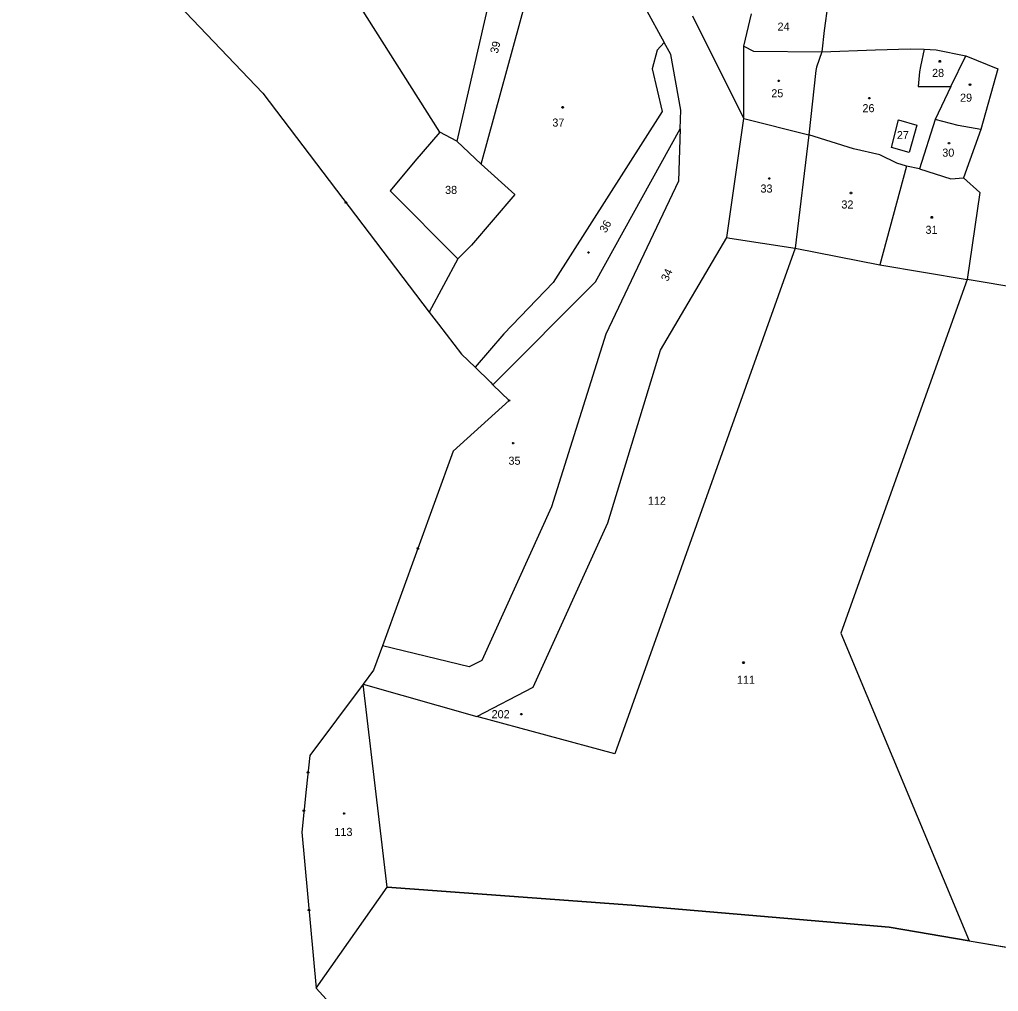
# Model space of a CAD drawing. Extents: x -841286 to -834997, y -1020681 to -1017810.
# Drawn here: x -838838.7 to -838632.6, y -1019442.2 to -1019237.6 of the extents above; entities that cross this region are included whole.
import ezdxf

# ---------------------------------------------------------------- set-up
doc = ezdxf.new("R2010")
doc.units = 0
for name, color, linetype in [('NERES_HRA', 7, 'Continuous'), ('OVNE_POP', 7, 'Continuous'), ('OVNE_PRE', 7, 'Continuous'), ('OVNE_SET', 7, 'Continuous'), ('OVNI_SET', 7, 'Continuous')]:
    doc.layers.add(name, color=color, linetype=linetype)

msp = doc.modelspace()

# ---------------------------------------------------------------- linework, layer by layer
at = {"layer": 'NERES_HRA'}
for points in [[(-838735.55, -1019317.63), (-838735.46, -1019317.78), (-838735.55, -1019317.93), (-838735.73, -1019317.93), (-838735.82, -1019317.78), (-838735.73, -1019317.63)], [(-838732.97, -1019383.7), (-838732.88, -1019383.85), (-838732.97, -1019384), (-838733.15, -1019384), (-838733.24, -1019383.85), (-838733.15, -1019383.7)]]:
    msp.add_lwpolyline(points, close=True, dxfattribs=at)
at = {"layer": 'OVNE_POP'}
for points in [[(-838644.84, -1019246.23), (-838644.75, -1019246.38), (-838644.84, -1019246.53), (-838645.02, -1019246.53), (-838645.11, -1019246.38), (-838645.02, -1019246.23)], [(-838678.75, -1019250.35), (-838678.66, -1019250.5), (-838678.75, -1019250.65), (-838678.93, -1019250.65), (-838679.02, -1019250.5), (-838678.93, -1019250.35)], [(-838638.49, -1019251.16), (-838638.4, -1019251.31), (-838638.49, -1019251.46), (-838638.67, -1019251.46), (-838638.76, -1019251.31), (-838638.67, -1019251.16)], [(-838659.69, -1019254.01), (-838659.6, -1019254.16), (-838659.69, -1019254.31), (-838659.87, -1019254.31), (-838659.96, -1019254.16), (-838659.87, -1019254.01)], [(-838724.28, -1019255.92), (-838724.19, -1019256.07), (-838724.28, -1019256.22), (-838724.46, -1019256.22), (-838724.55, -1019256.07), (-838724.46, -1019255.92)], [(-838642.91, -1019263.46), (-838642.82, -1019263.61), (-838642.91, -1019263.76), (-838643.09, -1019263.76), (-838643.18, -1019263.61), (-838643.09, -1019263.46)], [(-838680.77, -1019270.93), (-838680.68, -1019271.08), (-838680.77, -1019271.23), (-838680.95, -1019271.23), (-838681.04, -1019271.08), (-838680.95, -1019270.93)], [(-838663.56, -1019273.96), (-838663.47, -1019274.11), (-838663.56, -1019274.26), (-838663.74, -1019274.26), (-838663.83, -1019274.11), (-838663.74, -1019273.96)], [(-838646.52, -1019279.08), (-838646.43, -1019279.23), (-838646.52, -1019279.38), (-838646.7, -1019279.38), (-838646.79, -1019279.23), (-838646.7, -1019279.08)], [(-838718.84, -1019286.8), (-838719.02, -1019286.79), (-838719.09, -1019286.63), (-838719, -1019286.48), (-838718.82, -1019286.49), (-838718.75, -1019286.65)], [(-838734.7, -1019326.63), (-838734.61, -1019326.78), (-838734.7, -1019326.93), (-838734.88, -1019326.93), (-838734.97, -1019326.78), (-838734.88, -1019326.63)], [(-838686.19, -1019372.86), (-838686.1, -1019373.01), (-838686.19, -1019373.16), (-838686.37, -1019373.16), (-838686.46, -1019373.01), (-838686.37, -1019372.86)], [(-838770.29, -1019404.6), (-838770.2, -1019404.75), (-838770.29, -1019404.9), (-838770.47, -1019404.9), (-838770.56, -1019404.75), (-838770.47, -1019404.6)]]:
    msp.add_lwpolyline(points, close=True, dxfattribs=at)
at = {"layer": 'OVNE_SET'}
for p, q in [((-838838.73, -1019199.36), (-838787.51, -1019253.07)), ((-838750.24, -1019261.32), (-838786.82, -1019203.49)), ((-838736.62, -1019219.66), (-838746.67, -1019263.18)), ((-838741.51, -1019268.05), (-838729.31, -1019223.42)), ((-838668.52, -1019234.26), (-838669.3, -1019239.9)), ((-838706.95, -1019235.15), (-838702.95, -1019242.44)), ((-838686.21, -1019243.17), (-838684.61, -1019236.39)), ((-838686.19, -1019258.4), (-838696.96, -1019236.88)), ((-838669.3, -1019239.9), (-838669.76, -1019244.39)), ((-838702.95, -1019242.44), (-838704.47, -1019244.03)), ((-838701.59, -1019244.92), (-838702.95, -1019242.44)), ((-838704.47, -1019244.03), (-838705.5, -1019247.99)), ((-838686.21, -1019243.17), (-838684.14, -1019244.25)), ((-838686.19, -1019258.4), (-838686.21, -1019243.17)), ((-838684.14, -1019244.25), (-838669.76, -1019244.39)), ((-838669.76, -1019244.39), (-838670.89, -1019247.59)), ((-838669.76, -1019244.39), (-838658.46, -1019243.95)), ((-838658.46, -1019243.95), (-838651.15, -1019243.76)), ((-838651.15, -1019243.76), (-838648.2, -1019243.83)), ((-838648.2, -1019243.83), (-838649.02, -1019247.5)), ((-838648.2, -1019243.83), (-838645.67, -1019243.94)), ((-838645.67, -1019243.94), (-838639.47, -1019245.24)), ((-838699.49, -1019256.68), (-838701.59, -1019244.92)), ((-838642.58, -1019251.66), (-838639.47, -1019245.24)), ((-838639.47, -1019245.24), (-838632.7, -1019247.96)), ((-838705.5, -1019247.99), (-838703.41, -1019256.92)), ((-838671.02, -1019248.34), (-838672.55, -1019261.89)), ((-838670.89, -1019247.59), (-838671.02, -1019248.34)), ((-838649.18, -1019248.58), (-838649.5, -1019251.66)), ((-838649.02, -1019247.5), (-838649.18, -1019248.58)), ((-838632.7, -1019247.96), (-838636.26, -1019260.71)), ((-838649.5, -1019251.66), (-838642.58, -1019251.66)), ((-838642.58, -1019251.66), (-838645.94, -1019258.61)), ((-838787.51, -1019253.07), (-838752.47, -1019299.18)), ((-838703.41, -1019256.92), (-838726.35, -1019292.98)), ((-838699.61, -1019260.62), (-838699.49, -1019256.68)), ((-838689.81, -1019283.46), (-838686.19, -1019258.4)), ((-838686.19, -1019258.4), (-838672.55, -1019261.89)), ((-838655.14, -1019264.56), (-838653.65, -1019258.71)), ((-838653.65, -1019258.71), (-838649.75, -1019259.8)), ((-838645.94, -1019258.61), (-838649.24, -1019269.04)), ((-838641.05, -1019259.92), (-838645.94, -1019258.61)), ((-838717.47, -1019292.84), (-838699.61, -1019260.62)), ((-838699.61, -1019260.62), (-838699.94, -1019271.6)), ((-838649.75, -1019259.8), (-838651.36, -1019265.55)), ((-838636.26, -1019260.71), (-838641.05, -1019259.92)), ((-838636.26, -1019260.71), (-838639.91, -1019270.89)), ((-838750.24, -1019261.32), (-838755.47, -1019267.38)), ((-838746.67, -1019263.18), (-838750.24, -1019261.32)), ((-838746.67, -1019263.18), (-838741.51, -1019268.05)), ((-838672.55, -1019261.89), (-838675.37, -1019285.76)), ((-838663.14, -1019264.82), (-838672.55, -1019261.89)), ((-838657.55, -1019266.1), (-838663.14, -1019264.82)), ((-838651.36, -1019265.55), (-838655.14, -1019264.56)), ((-838755.47, -1019267.38), (-838760.71, -1019273.66)), ((-838653.96, -1019267.83), (-838657.55, -1019266.1)), ((-838741.51, -1019268.05), (-838734.45, -1019274.45)), ((-838651.95, -1019268.49), (-838657.58, -1019289.25)), ((-838651.95, -1019268.49), (-838653.96, -1019267.83)), ((-838649.24, -1019269.04), (-838651.95, -1019268.49)), ((-838649.24, -1019269.04), (-838642.6, -1019271.15)), ((-838642.6, -1019271.15), (-838639.91, -1019270.89)), ((-838639.91, -1019270.89), (-838636.5, -1019273.99)), ((-838699.94, -1019271.6), (-838715.24, -1019303.82)), ((-838760.71, -1019273.66), (-838746.45, -1019287.96)), ((-838734.45, -1019274.45), (-838743.57, -1019285.07)), ((-838636.5, -1019273.99), (-838639.19, -1019292.34)), ((-838703.75, -1019307.23), (-838689.81, -1019283.46)), ((-838689.81, -1019283.46), (-838689.17, -1019283.64)), ((-838689.17, -1019283.64), (-838675.37, -1019285.76)), ((-838743.57, -1019285.07), (-838746.45, -1019287.96)), ((-838675.37, -1019285.76), (-838713.34, -1019392.19)), ((-838675.37, -1019285.76), (-838657.58, -1019289.25)), ((-838746.45, -1019287.96), (-838752.47, -1019299.18)), ((-838657.58, -1019289.25), (-838639.19, -1019292.34)), ((-838739.03, -1019314.48), (-838717.47, -1019292.84)), ((-838726.35, -1019292.98), (-838736.75, -1019303.79)), ((-838639.19, -1019292.34), (-838665.76, -1019366.82)), ((-838592.81, -1019300.12), (-838639.19, -1019292.34)), ((-838752.47, -1019299.18), (-838750.51, -1019301.75)), ((-838750.51, -1019301.75), (-838745.63, -1019308.07)), ((-838736.75, -1019303.79), (-838742.82, -1019310.8)), ((-838715.24, -1019303.82), (-838726.74, -1019340.16)), ((-838745.63, -1019308.07), (-838742.82, -1019310.8)), ((-838714.88, -1019343.54), (-838703.75, -1019307.23)), ((-838742.82, -1019310.8), (-838739.56, -1019313.97)), ((-838739.56, -1019313.97), (-838739.03, -1019314.48)), ((-838739.03, -1019314.48), (-838735.64, -1019317.78)), ((-838735.64, -1019317.78), (-838747.42, -1019328.46)), ((-838747.42, -1019328.46), (-838762.3, -1019369.45)), ((-838726.74, -1019340.16), (-838741.41, -1019372.54)), ((-838730.55, -1019378.15), (-838714.88, -1019343.54)), ((-838665.76, -1019366.82), (-838638.75, -1019431.56)), ((-838762.3, -1019369.45), (-838764.17, -1019374.59)), ((-838744.03, -1019373.91), (-838762.3, -1019369.45)), ((-838741.41, -1019372.54), (-838744.03, -1019373.91)), ((-838764.17, -1019374.59), (-838766.36, -1019377.52)), ((-838766.36, -1019377.52), (-838777.6, -1019392.55)), ((-838766.36, -1019377.52), (-838742.45, -1019384.36)), ((-838761.34, -1019420.24), (-838766.36, -1019377.52)), ((-838742.45, -1019384.36), (-838730.55, -1019378.15)), ((-838713.34, -1019392.19), (-838742.45, -1019384.36)), ((-838777.6, -1019392.55), (-838778.36, -1019399.69)), ((-838778.36, -1019399.69), (-838779.32, -1019408.66)), ((-838779.32, -1019408.66), (-838776.24, -1019441.54)), ((-838776.24, -1019441.54), (-838761.34, -1019420.24)), ((-838709.81, -1019424.05), (-838761.34, -1019420.24)), ((-838655.6, -1019428.68), (-838709.81, -1019424.05)), ((-838638.75, -1019431.56), (-838655.6, -1019428.68)), ((-838638.75, -1019431.56), (-838621.56, -1019434.51)), ((-838776.24, -1019441.54), (-838743.93, -1019477.14))]:
    msp.add_line(p, q, dxfattribs=at)
for points in [[(-838769.82, -1019276.11), (-838769.88, -1019276.27), (-838770.06, -1019276.29), (-838770.16, -1019276.14), (-838770.1, -1019275.98), (-838769.92, -1019275.96)], [(-838754.75, -1019349.09), (-838754.92, -1019349.12), (-838755.03, -1019348.99), (-838754.97, -1019348.82), (-838754.8, -1019348.79), (-838754.69, -1019348.92)], [(-838777.84, -1019396.23), (-838778, -1019396.3), (-838778.14, -1019396.19), (-838778.12, -1019396.01), (-838777.96, -1019395.94), (-838777.82, -1019396.05)], [(-838778.7, -1019404.28), (-838778.86, -1019404.35), (-838779, -1019404.25), (-838778.98, -1019404.07), (-838778.82, -1019404), (-838778.68, -1019404.1)], [(-838777.62, -1019425.18), (-838777.76, -1019425.28), (-838777.92, -1019425.2), (-838777.94, -1019425.02), (-838777.8, -1019424.92), (-838777.64, -1019425)]]:
    msp.add_lwpolyline(points, close=True, dxfattribs=at)
at = {"layer": 'OVNI_SET'}
for points in [[(-838777.6, -1019392.55), (-838778.36, -1019399.69), (-838779.32, -1019408.66), (-838776.24, -1019441.54)], [(-838776.24, -1019441.54), (-838761.34, -1019420.24), (-838709.81, -1019424.05), (-838655.6, -1019428.68), (-838638.75, -1019431.56), (-838621.56, -1019434.51), (-838614.81, -1019434.56), (-838606, -1019437.1), (-838593.35, -1019440.42), (-838585.55, -1019440.4), (-838565, -1019435.94), (-838559.4, -1019435.95), (-838551.47, -1019434.81), (-838539.55, -1019431.48), (-838536.25, -1019430.7), (-838510.07, -1019442.9)]]:
    msp.add_lwpolyline(points, dxfattribs=at)

# ---------------------------------------------------------------- texts
at = {"layer": 'NERES_HRA'}
msp.add_text('202', height=1.7, dxfattribs=at).set_placement((-838739.32, -1019384.7))
at = {"layer": 'OVNE_PRE'}
for s, p in [('24', (-838679.11, -1019239.93)), ('28', (-838646.56, -1019249.68)), ('25', (-838680.42, -1019253.96)), ('29', (-838640.67, -1019254.89)), ('26', (-838661.22, -1019257.1)), ('37', (-838726.53, -1019260.13)), ('27', (-838653.98, -1019262.77)), ('30', (-838644.41, -1019266.46)), ('38', (-838749.12, -1019274.31)), ('33', (-838682.7, -1019274.02)), ('32', (-838665.66, -1019277.38)), ('31', (-838647.95, -1019282.71)), ('35', (-838735.77, -1019331.33)), ('112', (-838706.41, -1019339.75)), ('111', (-838687.65, -1019377.44)), ('113', (-838772.42, -1019409.48))]:
    msp.add_text(s, height=1.7, dxfattribs=at).set_placement(p)
for s, rotation, p in [('39', 76.4899, (-838738.02, -1019244.85)), ('36', 60.9054, (-838715.25, -1019282.65)), ('34', 64.9734, (-838702.22, -1019292.85))]:
    msp.add_text(s, height=1.7, rotation=rotation, dxfattribs=at).set_placement(p)

doc.saveas('drawing.dxf')
